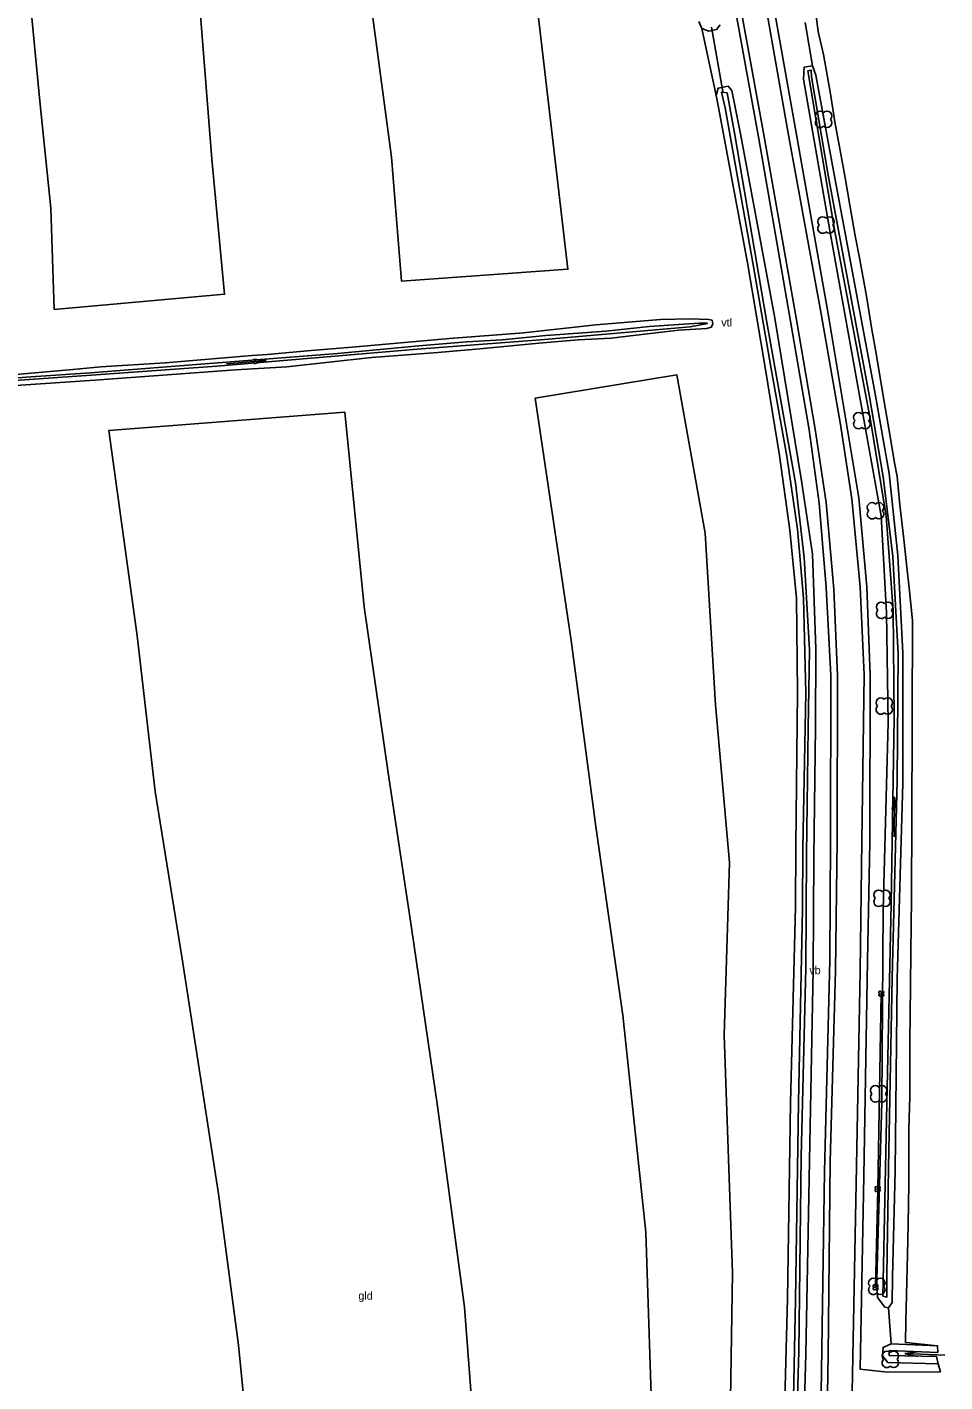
# Model space of a CAD drawing. Extents: x 154825 to 158680, y 370717 to 378075.
# Drawn here: x 157186.7 to 157301.3, y 373400.2 to 373569.5 of the extents above; entities that cross this region are included whole.
import ezdxf

# ---------------------------------------------------------------- set-up
doc = ezdxf.new("R2010")
doc.units = 0
for name, color, linetype in [('boom', 7, 'Continuous'), ('cultuurscheiding', 7, 'Continuous'), ('duiker lijn', 7, 'Continuous'), ('grasland_productiegrasl(vs)', 7, 'Continuous'), ('greppel - midden sloot', 7, 'Continuous'), ('hoogteverschillijn', 7, 'Continuous'), ('insteek sloot', 7, 'Continuous'), ('kant gesloten verharding', 7, 'Continuous'), ('kant onverhard', 7, 'Continuous'), ('maaiveldlijn algemeen - gesloten verharding', 7, 'Continuous'), ('maaiveldlijn algemeen - onverhard', 7, 'Continuous'), ('Sloot bodem', 7, 'Continuous'), ('stroomrichting  watergangen', 7, 'Continuous'), ('verharding algemeen', 7, 'Continuous'), ('verkeersb_z kabel', 7, 'Continuous'), ('vlak_Grasland', 7, 'Continuous'), ('vlak_Grazige_vegetatie', 7, 'Continuous')]:
    doc.layers.add(name, color=color, linetype=linetype)

msp = doc.modelspace()

# ---------------------------------------------------------------- linework, layer by layer
at = {"layer": 'boom'}
msp.add_lwpolyline([(157292.64, 373412.03), (157292.91, 373424.3), (157293.36, 373448.73)], dxfattribs=at)
for centre in [(157293.36, 373448.73), (157292.91, 373424.3), (157292.64, 373412.03)]:
    msp.add_circle(centre, 0.006, dxfattribs=at)
for centre, radius, start, end in [((157285.72, 373558.4), 0.6, 45, 225), ((157286.57, 373558.4), 0.6, 315, 135), ((157285.72, 373557.55), 0.6, 134.7431, 315), ((157286.57, 373557.55), 0.6, 225, 45), ((157286.02, 373545.18), 0.6, 45, 225), ((157286.87, 373545.18), 0.6, 315, 135), ((157286.02, 373544.33), 0.6, 134.7431, 315), ((157286.87, 373544.33), 0.6, 225, 45), ((157290.5, 373520.75), 0.6, 45, 225), ((157290.5, 373519.9), 0.6, 134.7431, 315), ((157291.35, 373520.75), 0.6, 315, 135), ((157291.35, 373519.9), 0.6, 225, 45), ((157292.21, 373509.48), 0.6, 45, 225), ((157293.06, 373509.48), 0.6, 315, 135), ((157292.21, 373508.64), 0.6, 134.7431, 315), ((157293.06, 373508.64), 0.6, 225, 45), ((157293.34, 373497.05), 0.6, 45, 225), ((157293.34, 373496.2), 0.6, 134.7431, 315), ((157294.19, 373497.05), 0.6, 315, 135), ((157294.19, 373496.2), 0.6, 225, 45), ((157293.3, 373485.08), 0.6, 45, 225), ((157293.3, 373484.23), 0.6, 134.7431, 315), ((157294.15, 373485.08), 0.6, 315, 135), ((157294.15, 373484.23), 0.6, 225, 45), ((157293.03, 373461.07), 0.6, 45, 225), ((157293.03, 373460.22), 0.6, 134.7431, 315), ((157293.88, 373461.07), 0.6, 315, 135), ((157293.88, 373460.22), 0.6, 225, 45), ((157293.21, 373448.88), 0.158, 357.075, 272.925), ((157293.52, 373448.88), 0.158, 267.075, 182.925), ((157293.21, 373448.57), 0.158, 87.075, 2.925), ((157293.52, 373448.57), 0.158, 177.075, 92.925), ((157292.61, 373436.63), 0.6, 45, 225), ((157293.45, 373436.63), 0.6, 315, 135), ((157292.61, 373435.78), 0.6, 134.7431, 315), ((157293.45, 373435.78), 0.6, 225, 45), ((157292.75, 373424.46), 0.158, 357.075, 272.925), ((157292.75, 373424.15), 0.158, 87.075, 2.925), ((157293.06, 373424.46), 0.158, 267.075, 182.925), ((157293.06, 373424.15), 0.158, 177.075, 92.925), ((157292.37, 373412.58), 0.6, 45, 225), ((157292.37, 373411.73), 0.6, 134.7431, 315), ((157292.48, 373412.19), 0.158, 357.075, 272.925), ((157292.48, 373411.87), 0.158, 87.075, 2.925), ((157292.8, 373412.19), 0.158, 267.075, 182.925), ((157292.8, 373411.87), 0.158, 177.075, 92.925), ((157293.22, 373412.58), 0.6, 315, 135), ((157293.22, 373411.73), 0.6, 225, 45), ((157294.05, 373403.45), 0.6, 45, 225), ((157294.9, 373403.45), 0.6, 315, 135), ((157294.05, 373402.6), 0.6, 134.7431, 315), ((157294.9, 373402.6), 0.6, 225, 45)]:
    msp.add_arc(centre, radius, start, end, dxfattribs=at)
at = {"layer": 'cultuurscheiding'}
for points in [[(157270.94, 373569.34), (157272.74, 373560.96)], [(157283.83, 373570.07), (157284.76, 373564.65)], [(157294.25, 373409.45), (157294.57, 373404.98)]]:
    msp.add_lwpolyline(points, dxfattribs=at)
at = {"layer": 'duiker lijn'}
msp.add_lwpolyline([(157273.55, 373561.43), (157272.13, 373569.47)], dxfattribs=at)
at = {"layer": 'greppel - midden sloot'}
for points in [[(157294.05, 373413.52), (157294.04, 373410.78), (157293.56, 373410.93), (157293.59, 373412.79), (157294.05, 373434.99), (157294.57, 373459.96), (157294.95, 373483.16), (157294.82, 373496.63), (157293.96, 373508.39), (157292.05, 373520.12), (157287.56, 373543.95), (157284.41, 373562.53), (157284.18, 373564.03), (157284.58, 373564.12), (157284.64, 373563.3), (157286.74, 373550.99), (157291.85, 373523.53), (157293.61, 373513.32), (157294.79, 373503.34), (157295.46, 373491.19), (157295.32, 373475.33), (157294.7, 373450.7), (157294.24, 373426.96), (157294.05, 373413.52)], [(157283.92, 373451.9), (157284, 373466.08), (157284.24, 373481.89), (157284.37, 373491.69), (157283.71, 373503.22), (157282.63, 373512.55), (157279.01, 373532.83), (157275.06, 373556.04), (157274.09, 373561.3), (157273.38, 373561.35), (157273.87, 373559.41), (157277.32, 373540.04), (157279.62, 373526.79), (157281.57, 373515.87), (157282.9, 373506.78), (157283.65, 373498.16), (157283.91, 373486.25), (157283.55, 373466.96), (157283.51, 373459.34)], [(157300.25, 373403.37), (157294.36, 373403.5), (157294.34, 373404.13), (157300.41, 373403.9)]]:
    msp.add_lwpolyline(points, dxfattribs=at)
at = {"layer": 'hoogteverschillijn'}
for points in [[(157187.01, 373573.33), (157188.26, 373560.24), (157189.64, 373546.88), (157190.05, 373534.21), (157211.32, 373536.11), (157209.74, 373552.98), (157208.62, 373567.28), (157207.45, 373582.02)], [(157229.74, 373571.61), (157232.17, 373553.25), (157233.43, 373537.75), (157254.21, 373539.23), (157252.08, 373557.51), (157249.89, 373576.42)], [(157285.16, 373571.16), (157285.49, 373568.95), (157286.13, 373566.07), (157287, 373561.14), (157287.57, 373557.65), (157288.22, 373554.09), (157288.85, 373550.67), (157289.44, 373547.25), (157290.11, 373543.43), (157290.62, 373540.65), (157291.49, 373535.86), (157292.18, 373531.7), (157292.71, 373528.7), (157293.59, 373523.42), (157294.3, 373519.32), (157295.04, 373514.84), (157295.34, 373513.33), (157295.67, 373509.82), (157296.16, 373505.5), (157296.58, 373501.66), (157296.82, 373499.43), (157297.27, 373495.35), (157297.27, 373494.81), (157297.24, 373491.47), (157297.2, 373487.29), (157297.22, 373482.94), (157297.22, 373479.98), (157297.16, 373472.78), (157297.19, 373467.72), (157297.13, 373463.77), (157297.12, 373460.58), (157297.06, 373453.92), (157297.02, 373449.64), (157296.91, 373442.61), (157296.92, 373441.06), (157296.94, 373435.88), (157296.8, 373431.78), (157296.78, 373424.94), (157296.7, 373419.88), (157296.62, 373416.07), (157296.43, 373407.77), (157296.38, 373405.15)], [(157264.63, 373398.61), (157263.96, 373418.94), (157261.08, 373446.03), (157257.68, 373469.62), (157254.63, 373492.83), (157250.14, 373523.12), (157267.83, 373526.04), (157271.36, 373506.26), (157272.63, 373484.83), (157274.39, 373465.12), (157273.75, 373443.52), (157274.77, 373413.84), (157274.4, 373390.12)], [(157215.47, 373380.26), (157213.05, 373404.79), (157210.55, 373423.71), (157206.04, 373453.08), (157202.66, 373473.99), (157200.39, 373493.43), (157196.88, 373519.1), (157226.36, 373521.38), (157228.78, 373497.05), (157231.76, 373476.32), (157234.66, 373456.93), (157237.93, 373434.66), (157241.3, 373409.56), (157242.61, 373392)]]:
    msp.add_lwpolyline(points, dxfattribs=at)
at = {"layer": 'insteek sloot'}
for points in [[(157273.25, 373569.76), (157272.78, 373569.2), (157271.82, 373568.99), (157270.94, 373569.34), (157270.56, 373570.21)], [(157294.77, 373413.34), (157294.7, 373410.12), (157294.25, 373409.45), (157293.8, 373409.56), (157292.89, 373410.76), (157292.78, 373412.99), (157293.41, 373435.19), (157293.6, 373459.22), (157294.21, 373482.61), (157294, 373496.29), (157293.35, 373508.44), (157286.97, 373543.82), (157283.64, 373563.01), (157283.74, 373564.5), (157284.76, 373564.65), (157285.17, 373563.51), (157287.38, 373551.54), (157292.61, 373523.68), (157294.34, 373513.71), (157295.41, 373503.47), (157296.05, 373491.33), (157296.05, 373475.02), (157295.35, 373450.57), (157295.09, 373426.55), (157294.77, 373413.34)], [(157280.95, 373383.91), (157281.66, 373410.57), (157282, 373435.07), (157282.65, 373459.59), (157282.68, 373467.17), (157282.87, 373486.38), (157282.78, 373498.14), (157281.94, 373506.65), (157280.66, 373515.95), (157278.88, 373526.7), (157276.64, 373540.03), (157273.06, 373559.26), (157272.74, 373560.96), (157272.99, 373561.87), (157274.22, 373562.11), (157274.69, 373561.58), (157275.76, 373556.16), (157280.03, 373533.39), (157283.4, 373512.8), (157284.76, 373503.65), (157285.16, 373491.83), (157285.12, 373482.08), (157284.91, 373465.74), (157284.86, 373451.73), (157284.38, 373427.85), (157283.92, 373403.67), (157283.31, 373381.69)], [(157184.34, 373526), (157192.36, 373526.71), (157195.85, 373527.04), (157203.91, 373527.56), (157214.76, 373528.46), (157216.63, 373528.58), (157222.13, 373529.1), (157227.25, 373529.52), (157239.43, 373530.6), (157248.67, 373531.28), (157257.72, 373532.3), (157265.76, 373532.96), (157269.48, 373533.03), (157271.82, 373532.95), (157272.22, 373532.87), (157272.32, 373532.38), (157272.11, 373532), (157271.55, 373531.84), (157268.06, 373531.62), (157264.48, 373531.22), (157259.6, 373530.63), (157255.5, 373530.4), (157250.57, 373530), (157243.68, 373529.34), (157237.97, 373528.82), (157229.66, 373528.23), (157219.1, 373527.05), (157212.7, 373526.67), (157195.14, 373525.38), (157182.75, 373524.53)], [(157300.45, 373402.48), (157294.17, 373402.65), (157293.52, 373403.48), (157293.57, 373404.52), (157294.57, 373404.98), (157300.39, 373404.73)]]:
    msp.add_lwpolyline(points, dxfattribs=at)
at = {"layer": 'kant gesloten verharding'}
for points in [[(157234.99, 373799.65), (157236.46, 373790.97), (157237.02, 373789.67), (157239.16, 373777.36), (157243.31, 373753.9), (157247.91, 373728.21), (157252.35, 373703.62), (157256.48, 373680.2), (157260.78, 373656), (157265.2, 373631.26), (157268.02, 373615.36), (157270.03, 373604.63), (157274.41, 373579.63), (157278.75, 373555.56), (157282.75, 373532.9), (157285.09, 373519.25), (157286.46, 373510.1), (157287.41, 373499.26), (157287.89, 373488.51), (157287.84, 373467.95), (157287.62, 373451.56)], [(157239.04, 373797.41), (157239.97, 373792.3), (157239.89, 373791.79), (157240.11, 373789.5), (157242.2, 373777.85), (157246.32, 373754.67), (157251.01, 373728.42), (157255.3, 373704.14), (157259.48, 373680.56), (157263.81, 373656.35), (157268.25, 373631.5), (157271.46, 373613.61), (157272.9, 373606.2), (157277.52, 373580.19), (157281.74, 373556.24), (157285.84, 373533.66), (157288.28, 373519.85), (157289.68, 373510.54), (157290.7, 373499.55), (157291.22, 373488.58), (157290.92, 373467.79), (157290.73, 373451.57)]]:
    msp.add_lwpolyline(points, dxfattribs=at)
at = {"layer": 'kant onverhard'}
for points in [[(157291.64, 373452.81), (157291.91, 373467.62), (157291.95, 373488.53), (157291.55, 373499.54), (157290.53, 373510.69), (157289.03, 373519.91), (157286.71, 373533.68), (157282.74, 373556.28), (157278.44, 373580.46), (157273.8, 373606.81), (157269.34, 373631.64), (157264.96, 373656.56), (157260.67, 373680.85), (157256.32, 373704.35), (157252.03, 373728.68), (157247.33, 373755.13), (157243.05, 373777.94), (157240.62, 373791.92), (157239.54, 373798.09)], [(157273.72, 373579.41), (157278.07, 373555.52), (157282.03, 373532.77), (157284.34, 373519.19), (157285.58, 373510.03), (157286.47, 373499.48), (157287.05, 373488.49), (157287.03, 373467.9), (157286.91, 373452.88)], [(157290.71, 373401.81), (157294.15, 373401.41), (157300.74, 373401.47)]]:
    msp.add_lwpolyline(points, dxfattribs=at)
at = {"layer": 'maaiveldlijn algemeen - gesloten verharding'}
for points in [[(157287.62, 373451.56), (157286.97, 373427.74), (157286.71, 373403.55), (157286.34, 373382.08), (157285.87, 373360.32), (157285.54, 373336.36), (157285.09, 373311.86), (157285.04, 373298.94), (157284.85, 373285), (157284.51, 373283.09), (157283.84, 373281.51), (157283.08, 373280.3), (157282.12, 373279.38), (157281.05, 373278.65), (157279.67, 373278.05), (157278.36, 373277.65), (157277.18, 373277.38)], [(157290.73, 373451.57), (157290.27, 373427.19), (157289.8, 373403.3), (157289.37, 373381.66), (157289.01, 373360.15), (157288.66, 373336.15), (157288.38, 373311.65), (157288.48, 373298.66), (157288.39, 373284.94), (157288.35, 373273.86), (157287.89, 373261.66), (157287.56, 373253.44), (157287.8, 373252.82)]]:
    msp.add_lwpolyline(points, dxfattribs=at)
at = {"layer": 'maaiveldlijn algemeen - onverhard'}
for points in [[(157286.91, 373452.88), (157286.28, 373426.51), (157285.84, 373398.84), (157285.37, 373372.14), (157284.82, 373345.6), (157284.43, 373320.39), (157284.15, 373298.43), (157283.91, 373284.88), (157282.95, 373282.12), (157281.95, 373280.75), (157280.4, 373279.39), (157278.36, 373278.06)], [(157291.64, 373452.81), (157291.17, 373425.95), (157290.71, 373401.81)]]:
    msp.add_lwpolyline(points, dxfattribs=at)
at = {"layer": 'Sloot bodem'}
for points in [[(157181.63, 373525.37), (157187.14, 373525.81), (157194.57, 373526.3), (157205.17, 373527.11), (157215.8, 373527.96), (157225.43, 373528.71), (157235.59, 373529.68), (157241.58, 373530.17), (157245.98, 373530.43), (157251.45, 373530.95), (157258.94, 373531.52), (157264.35, 373532.08), (157268.69, 373532.37), (157270.64, 373532.49), (157271.52, 373532.49), (157271.64, 373532.45), (157269.48, 373532.04), (157250.79, 373530.44), (157235.4, 373529.24), (157224.62, 373528.33), (157210.36, 373527.14), (157195.23, 373526.06), (157180.38, 373524.99)], [(157283.92, 373451.9), (157283.34, 373428.36), (157283.05, 373403.99), (157282.4, 373381.72), (157281.94, 373361.28), (157281.43, 373336.42), (157280.96, 373311.9), (157280.86, 373298.76), (157280.84, 373284.13), (157279.87, 373283.87), (157279.91, 373285.42), (157280.4, 373303.59), (157280.68, 373329.65), (157281.26, 373357.17), (157282.08, 373383.96), (157282.63, 373410.47), (157283.01, 373435.14), (157283.51, 373459.34)]]:
    msp.add_lwpolyline(points, dxfattribs=at)
at = {"layer": 'stroomrichting  watergangen'}
for p, q in [((157211.55, 373527.44), (157216.53, 373527.83)), ((157216.52, 373527.84), (157214.94, 373527.99)), ((157216.53, 373527.83), (157215, 373527.43)), ((157294.98, 373473.29), (157294.7, 373471.73)), ((157294.98, 373468.31), (157295, 373473.3)), ((157295, 373473.3), (157295.27, 373471.75)), ((157296.31, 373403.74), (157297.87, 373403.96)), ((157301.3, 373403.56), (157296.31, 373403.74)), ((157296.32, 373403.72), (157297.87, 373403.39))]:
    msp.add_line(p, q, dxfattribs=at)
at = {"layer": 'vlak_Grasland'}
for points in [[(157285.16, 373571.16), (157285.49, 373568.95), (157286.13, 373566.07), (157287, 373561.14), (157287.57, 373557.65), (157288.22, 373554.09), (157288.85, 373550.67), (157289.44, 373547.25), (157290.11, 373543.43), (157290.62, 373540.65), (157291.49, 373535.86), (157292.18, 373531.7), (157292.71, 373528.7), (157293.59, 373523.42), (157294.3, 373519.32), (157295.04, 373514.84), (157295.34, 373513.33), (157295.67, 373509.82), (157296.16, 373505.5), (157296.58, 373501.66), (157296.82, 373499.43), (157297.27, 373495.35), (157297.27, 373494.81), (157297.24, 373491.47), (157297.2, 373487.29), (157297.22, 373482.94), (157297.22, 373479.98), (157297.16, 373472.78), (157297.19, 373467.72), (157297.13, 373463.77), (157297.12, 373460.58), (157297.06, 373453.92), (157297.02, 373449.64), (157296.91, 373442.61), (157296.92, 373441.06), (157296.94, 373435.88), (157296.8, 373431.78), (157296.78, 373424.94), (157296.7, 373419.88), (157296.62, 373416.07), (157296.43, 373407.77), (157296.38, 373405.15), (157300.39, 373404.73), (157294.57, 373404.98), (157294.25, 373409.45), (157294.7, 373410.12), (157294.77, 373413.34), (157295.09, 373426.55), (157295.35, 373450.57), (157296.05, 373475.02), (157296.05, 373491.33), (157295.41, 373503.47), (157294.34, 373513.71), (157292.61, 373523.68), (157287.38, 373551.54), (157285.17, 373563.51), (157284.76, 373564.65), (157283.83, 373570.07)], [(157270.56, 373570.21), (157270.94, 373569.34), (157272.74, 373560.96), (157273.06, 373559.26), (157276.64, 373540.03), (157278.88, 373526.7), (157280.66, 373515.95), (157281.94, 373506.65), (157282.78, 373498.14), (157282.87, 373486.38), (157282.68, 373467.17), (157282.65, 373459.59), (157282, 373435.07), (157281.66, 373410.57), (157280.95, 373383.91)], [(157182.75, 373524.53), (157195.14, 373525.38), (157212.7, 373526.67), (157219.1, 373527.05), (157229.66, 373528.23), (157237.97, 373528.82), (157243.68, 373529.34), (157250.57, 373530), (157255.5, 373530.4), (157259.6, 373530.63), (157264.48, 373531.22), (157268.06, 373531.62), (157271.55, 373531.84), (157272.11, 373532), (157272.32, 373532.38), (157272.22, 373532.87), (157271.82, 373532.95), (157269.48, 373533.03), (157265.76, 373532.96), (157257.72, 373532.3), (157248.67, 373531.28), (157239.43, 373530.6), (157227.25, 373529.52), (157222.13, 373529.1), (157216.63, 373528.58), (157214.76, 373528.46), (157203.91, 373527.56), (157195.85, 373527.04), (157192.36, 373526.71), (157184.34, 373526)]]:
    msp.add_lwpolyline(points, dxfattribs=at)
at = {"layer": 'vlak_Grazige_vegetatie'}
for points in [[(157273.72, 373579.41), (157278.07, 373555.52), (157282.03, 373532.77), (157284.34, 373519.19), (157285.58, 373510.03), (157286.47, 373499.48), (157287.05, 373488.49), (157287.03, 373467.9), (157286.91, 373452.88), (157286.28, 373426.51), (157285.84, 373398.84)], [(157283.83, 373570.07), (157284.76, 373564.65), (157283.74, 373564.5), (157283.64, 373563.01), (157286.97, 373543.82), (157293.35, 373508.44), (157294, 373496.29), (157294.21, 373482.61), (157293.6, 373459.22), (157293.41, 373435.19), (157292.78, 373412.99), (157292.89, 373410.76), (157293.8, 373409.56), (157294.25, 373409.45), (157294.57, 373404.98), (157293.57, 373404.52), (157293.52, 373403.48), (157294.17, 373402.65), (157300.45, 373402.48), (157300.74, 373401.47), (157294.15, 373401.41), (157290.71, 373401.81), (157291.17, 373425.95), (157291.64, 373452.81), (157291.91, 373467.62), (157291.95, 373488.53), (157291.55, 373499.54), (157290.53, 373510.69), (157289.03, 373519.91), (157286.71, 373533.68), (157282.74, 373556.28), (157278.44, 373580.46)], [(157273.25, 373569.76), (157272.78, 373569.2), (157271.82, 373568.99), (157270.94, 373569.34), (157270.56, 373570.21)], [(157283.31, 373381.69), (157283.92, 373403.67), (157284.38, 373427.85), (157284.86, 373451.73), (157284.91, 373465.74), (157285.12, 373482.08), (157285.16, 373491.83), (157284.76, 373503.65), (157283.4, 373512.8), (157280.03, 373533.39), (157275.76, 373556.16), (157274.69, 373561.58), (157274.22, 373562.11), (157272.99, 373561.87), (157272.74, 373560.96), (157270.94, 373569.34), (157271.82, 373568.99), (157272.78, 373569.2), (157273.25, 373569.76)], [(157280.95, 373383.91), (157281.66, 373410.57), (157282, 373435.07), (157282.65, 373459.59), (157282.68, 373467.17), (157282.87, 373486.38), (157282.78, 373498.14), (157281.94, 373506.65), (157280.66, 373515.95), (157278.88, 373526.7), (157276.64, 373540.03), (157273.06, 373559.26), (157272.74, 373560.96), (157272.99, 373561.87), (157274.22, 373562.11), (157274.69, 373561.58), (157275.76, 373556.16), (157280.03, 373533.39), (157283.4, 373512.8), (157284.76, 373503.65), (157285.16, 373491.83), (157285.12, 373482.08), (157284.91, 373465.74), (157284.86, 373451.73), (157284.38, 373427.85), (157283.92, 373403.67), (157283.31, 373381.69)], [(157282.4, 373381.72), (157283.05, 373403.99), (157283.34, 373428.36), (157283.92, 373451.9), (157284, 373466.08), (157284.24, 373481.89), (157284.37, 373491.69), (157283.71, 373503.22), (157282.63, 373512.55), (157279.01, 373532.83), (157275.06, 373556.04), (157274.09, 373561.3), (157273.38, 373561.35), (157273.87, 373559.41), (157277.32, 373540.04), (157279.62, 373526.79), (157281.57, 373515.87), (157282.9, 373506.78), (157283.65, 373498.16), (157283.91, 373486.25), (157283.55, 373466.96), (157283.51, 373459.34), (157283.01, 373435.14), (157282.63, 373410.47), (157282.08, 373383.96)], [(157180.38, 373524.99), (157195.23, 373526.06), (157210.36, 373527.14), (157224.62, 373528.33), (157235.4, 373529.24), (157250.79, 373530.44), (157269.48, 373532.04), (157271.64, 373532.45), (157271.52, 373532.49), (157270.64, 373532.49), (157268.69, 373532.37), (157264.35, 373532.08), (157258.94, 373531.52), (157251.45, 373530.95), (157245.98, 373530.43), (157241.58, 373530.17), (157235.59, 373529.68), (157225.43, 373528.71), (157215.8, 373527.96), (157205.17, 373527.11), (157194.57, 373526.3), (157187.14, 373525.81), (157181.63, 373525.37)], [(157184.34, 373526), (157192.36, 373526.71), (157195.85, 373527.04), (157203.91, 373527.56), (157214.76, 373528.46), (157216.63, 373528.58), (157222.13, 373529.1), (157227.25, 373529.52), (157239.43, 373530.6), (157248.67, 373531.28), (157257.72, 373532.3), (157265.76, 373532.96), (157269.48, 373533.03), (157271.82, 373532.95), (157272.22, 373532.87), (157272.32, 373532.38), (157272.11, 373532), (157271.55, 373531.84), (157268.06, 373531.62), (157264.48, 373531.22), (157259.6, 373530.63), (157255.5, 373530.4), (157250.57, 373530), (157243.68, 373529.34), (157237.97, 373528.82), (157229.66, 373528.23), (157219.1, 373527.05), (157212.7, 373526.67), (157195.14, 373525.38), (157182.75, 373524.53)]]:
    msp.add_lwpolyline(points, dxfattribs=at)
for points in [[(157284.76, 373564.65), (157285.17, 373563.51), (157287.38, 373551.54), (157292.61, 373523.68), (157294.34, 373513.71), (157295.41, 373503.47), (157296.05, 373491.33), (157296.05, 373475.02), (157295.35, 373450.57), (157295.09, 373426.55), (157294.77, 373413.34), (157294.7, 373410.12), (157294.25, 373409.45), (157293.8, 373409.56), (157292.89, 373410.76), (157292.78, 373412.99), (157293.41, 373435.19), (157293.6, 373459.22), (157294.21, 373482.61), (157294, 373496.29), (157293.35, 373508.44), (157286.97, 373543.82), (157283.64, 373563.01), (157283.74, 373564.5)], [(157293.56, 373410.93), (157294.04, 373410.78), (157294.05, 373413.52), (157294.24, 373426.96), (157294.7, 373450.7), (157295.32, 373475.33), (157295.46, 373491.19), (157294.79, 373503.34), (157293.61, 373513.32), (157291.85, 373523.53), (157286.74, 373550.99), (157284.64, 373563.3), (157284.58, 373564.12), (157284.18, 373564.03), (157284.41, 373562.53), (157287.56, 373543.95), (157292.05, 373520.12), (157293.96, 373508.39), (157294.82, 373496.63), (157294.95, 373483.16), (157294.57, 373459.96), (157294.05, 373434.99), (157293.59, 373412.79)], [(157300.39, 373404.73), (157300.41, 373403.9), (157294.34, 373404.13), (157294.36, 373403.5), (157300.25, 373403.37), (157300.45, 373402.48), (157294.17, 373402.65), (157293.52, 373403.48), (157293.57, 373404.52), (157294.57, 373404.98)]]:
    msp.add_lwpolyline(points, close=True, dxfattribs=at)

# ---------------------------------------------------------------- texts
at = {"layer": 'grasland_productiegrasl(vs)'}
msp.add_text('gld', height=1, dxfattribs=at).set_placement((157228.04, 373410.48))
at = {"layer": 'verharding algemeen'}
msp.add_text('vtl', height=1, dxfattribs=at).set_placement((157273.37, 373532.09))
at = {"layer": 'verkeersb_z kabel'}
msp.add_text('vb', height=1, dxfattribs=at).set_placement((157284.37, 373451.15))

doc.saveas('drawing.dxf')
